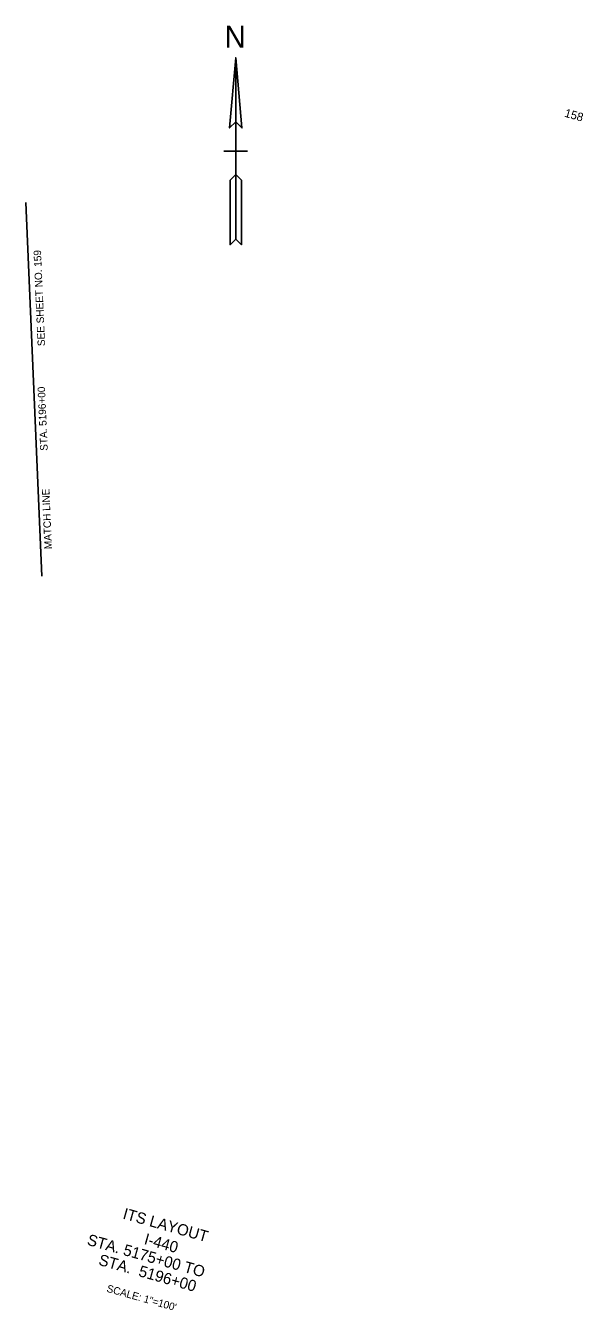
# Model space of a CAD drawing. Extents: x -200 to 1735303, y -325 to 650534.
# Drawn here: x 1734408 to 1735303, y 648472 to 650534 of the extents above; entities that cross this region are included whole.
import ezdxf

# ---------------------------------------------------------------- set-up
doc = ezdxf.new("R2010")
doc.units = 0
for name, color, linetype in [('DESIGN - CENTERLINE - Proposed Text', 7, 'Continuous'), ('DESIGN - SCRATCH - User 1', 7, 'Continuous'), ('DESIGN - SHEET - Corner Text', 7, 'Continuous'), ('ITS - CONST TEXT', 7, 'Continuous'), ('ITS - EXISITING WEATHER STATION', 7, 'Continuous'), ('ITS - EXISTING COMM CABLE', 7, 'Continuous'), ('ITS - EXISTING HAR', 7, 'Continuous')]:
    doc.layers.add(name, color=color, linetype=linetype)

msp = doc.modelspace()

# ---------------------------------------------------------------- linework, layer by layer
at = {"layer": 'DESIGN - CENTERLINE - Proposed Text'}
for p, q in [((1734745.1, 650332.1), (1734726.2, 650332.1)), ((1734764, 650332.1), (1734745.1, 650332.1))]:
    msp.add_line(p, q, dxfattribs=at)
msp.add_lwpolyline([(1734745.1, 650482.1), (1734735.3, 650369.5), (1734745.1, 650379.3), (1734754.9, 650369.5), (1734745.1, 650482.1), (1734745.1, 650191.2), (1734754.2, 650182.1), (1734754.2, 650285.6), (1734745.1, 650294.7), (1734736, 650285.6), (1734736, 650182.1), (1734745.1, 650191.2)], dxfattribs=at)
for points in [[(1734745.1, 650379.3), (1734754.9, 650369.5), (1734745.1, 650482.1)], [(1734736, 650182.1), (1734745.1, 650191.2), (1734745.1, 650294.7), (1734736, 650285.6)]]:
    msp.add_lwpolyline(points, close=True, dxfattribs=at)
at = {"layer": 'DESIGN - SCRATCH - User 1'}
for p, q in [((1734636.9, 648563.5), (1734636.9, 648563.5)), ((1734636.9, 648563.5), (1734636.9, 648563.5)), ((1734635.6, 648546.8), (1734635.6, 648546.8))]:
    msp.add_line(p, q, dxfattribs=at)
at = {"layer": 'ITS - EXISITING WEATHER STATION'}
msp.add_line((1734636.8, 648563.6), (1734636.8, 648563.6), dxfattribs=at)
msp.add_line((1734636.8, 648563.6), (1734636.8, 648563.6), dxfattribs=at)
at = {"layer": 'ITS - EXISTING COMM CABLE'}
msp.add_line((1734434.1, 649650.6), (1734408, 650250), dxfattribs=at)

# ---------------------------------------------------------------- texts
at = {"layer": 'DESIGN - CENTERLINE - Proposed Text'}
msp.add_text('N', height=35.4, dxfattribs=at).set_placement((1734727, 650498.2))
at = {"layer": 'DESIGN - SHEET - Corner Text'}
msp.add_text('158', height=13.5, rotation=344.2665, dxfattribs=at).set_placement((1735271.8, 650387.7))
at = {"layer": 'ITS - CONST TEXT'}
msp.add_text('SCALE: 1"=100\'', height=12, rotation=344.2666, dxfattribs=at).set_placement((1734537, 648502.3))
at = {"layer": 'ITS - EXISTING COMM CABLE'}
for s, p in [('SEE SHEET NO. 159 ', (1734439.2, 650019.7)), ('STA. 5196+00', (1734443.4, 649851.7)), ('MATCH LINE', (1734450.2, 649693.9))]:
    msp.add_text(s, height=12, rotation=92.4969, dxfattribs=at).set_placement(p)
at = {"layer": 'ITS - EXISTING HAR'}
for s, p in [('ITS LAYOUT', (1734562.7, 648619.7)), ('STA. 5175+00 TO', (1734505.3, 648577.8)), ('I-440', (1734596.9, 648579)), ('STA.  5196+00', (1734523.6, 648545.6))]:
    msp.add_text(s, height=18, rotation=344.2666, dxfattribs=at).set_placement(p)

doc.saveas('drawing.dxf')
